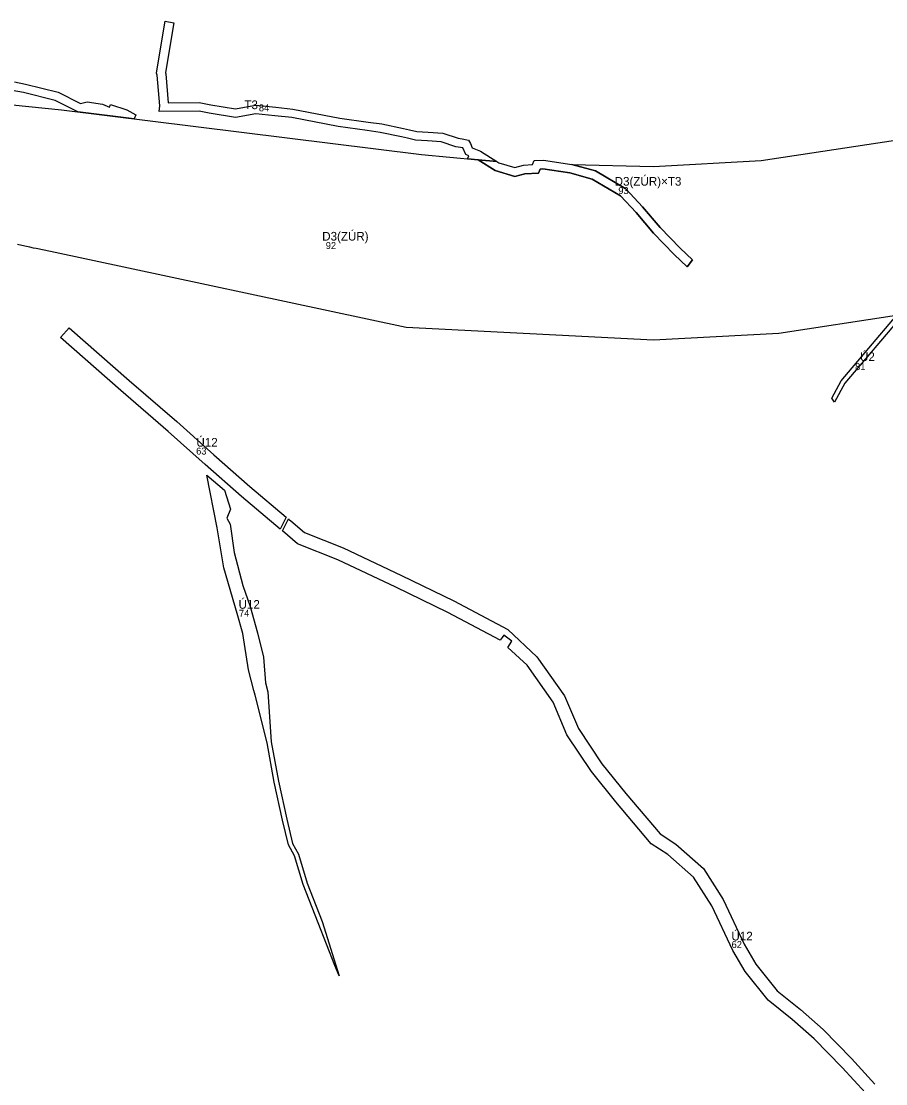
# Model space of a CAD drawing. Extents: x -521621 to -516857, y -1190025 to -1185894.
# Drawn here: x -519468 to -518471, y -1188636 to -1187411 of the extents above; entities that cross this region are included whole.
import ezdxf

# ---------------------------------------------------------------- set-up
doc = ezdxf.new("R2010")
doc.units = 0
for name, color, linetype in [('VPO_id', 7, 'Continuous'), ('VPO_n', 7, 'Continuous'), ('VPS_id', 7, 'Continuous'), ('VPS_n', 7, 'Continuous')]:
    doc.layers.add(name, color=color, linetype=linetype)

msp = doc.modelspace()

# ---------------------------------------------------------------- linework, layer by layer
at = {"layer": 'VPO_n'}
for points in [[(-518451.1, -1187749.3), (-518518.3, -1187828.7), (-518530, -1187850.3), (-518533.4, -1187846), (-518522.5, -1187825.9), (-518458.6, -1187750.5)], [(-519422.5, -1187776), (-519415.6, -1187768.2), (-519412.6, -1187764.7), (-519343.3, -1187825.6), (-519288.3, -1187872.8), (-519249.5, -1187907.6), (-519245.6, -1187911), (-519204.1, -1187947.8), (-519162.2, -1187983), (-519169.2, -1187996.7), (-519213.9, -1187959.1), (-519255.6, -1187922.2), (-519298.2, -1187884.1), (-519353.1, -1187836.9)], [(-519253.8, -1187934.5), (-519233.6, -1187951.8), (-519226.6, -1187973.9), (-519230.7, -1187984), (-519226.7, -1187990.9), (-519222.4, -1188023.6), (-519212.2, -1188061.6), (-519204, -1188086.1), (-519195.2, -1188116.4), (-519188.6, -1188144.5), (-519186.1, -1188173.9), (-519183.4, -1188184.3), (-519179.6, -1188242), (-519171.1, -1188287.2), (-519161.6, -1188331.1), (-519155.1, -1188358.9), (-519148.3, -1188371.3), (-519138.1, -1188404.6), (-519120.9, -1188448.8), (-519101.2, -1188511.7), (-519106.4, -1188499.6), (-519125.6, -1188450.6), (-519142.9, -1188406.3), (-519152.9, -1188373.2), (-519159.8, -1188360.8), (-519166.5, -1188332.2), (-519176, -1188288.2), (-519184.4, -1188243.1), (-519198.2, -1188188.1), (-519199.6, -1188182.6), (-519205.9, -1188159.1), (-519212.1, -1188117.2), (-519218.9, -1188094), (-519234, -1188041.5), (-519242, -1187995.2)]]:
    msp.add_lwpolyline(points, close=True, dxfattribs=at)
msp.add_lwpolyline([(-518494.6, -1188646.3), (-518521.3, -1188617.2), (-518553.6, -1188584.3), (-518578.9, -1188561.9), (-518606.8, -1188539.5), (-518633, -1188506.5), (-518647.5, -1188482.3), (-518671.6, -1188430.9), (-518692.6, -1188397.9), (-518722.2, -1188371.9), (-518741.4, -1188359.3), (-518782.4, -1188311.1), (-518810.5, -1188276.1), (-518838.6, -1188233.7), (-518854.5, -1188196.2), (-518884.6, -1188153.7), (-518906.7, -1188133.1), (-518902, -1188126), (-518906.7, -1188122.4), (-518911.4, -1188118.8), (-518913.4, -1188121.8), (-518915.5, -1188124.9), (-518975.8, -1188092.8), (-519035.8, -1188063.6), (-519102.8, -1188032), (-519149.1, -1188013.6), (-519166.7, -1187998.8), (-519159.8, -1187985), (-519159.6, -1187985.2), (-519157, -1187987.3), (-519141.3, -1188000.6), (-519096.8, -1188018.2), (-519029.3, -1188050.1), (-518969, -1188079.4), (-518906.7, -1188112.5), (-518873.2, -1188143.8), (-518841.3, -1188188.8), (-518825.3, -1188226.5), (-518798.4, -1188267.3), (-518770.9, -1188301.6), (-518731.3, -1188347.9), (-518713.1, -1188360), (-518681.1, -1188388), (-518658.4, -1188423.7), (-518634.3, -1188475.2), (-518620.7, -1188498), (-518596.1, -1188528.9), (-518569.2, -1188550.4), (-518543.2, -1188573.4), (-518510.4, -1188606.8), (-518483.5, -1188636.3)], dxfattribs=at)
at = {"layer": 'VPS_n'}
for points in [[(-519306.3, -1187438.7), (-519301.7, -1187411.4), (-519291.8, -1187413.4), (-519296.5, -1187440.4), (-519301.5, -1187470.9), (-519301.2, -1187472.1), (-519298.2, -1187505.3), (-519262.5, -1187504.9), (-519249.3, -1187507.6), (-519220.9, -1187512.2), (-519197.7, -1187508), (-519174.4, -1187510.5), (-519154.5, -1187512.6), (-519100.6, -1187523), (-519067.6, -1187527.6), (-519052.2, -1187529.7), (-519027.2, -1187534.9), (-519020.2, -1187536.4), (-519011.6, -1187538.6), (-518998.6, -1187539.3), (-518981.7, -1187540.5), (-518964.2, -1187546.2), (-518959.5, -1187546.9), (-518952.3, -1187548.3), (-518950, -1187552.2), (-518947.7, -1187557.3), (-518938.1, -1187561), (-518919.5, -1187573), (-518941, -1187571), (-518953.1, -1187569.9), (-518951.6, -1187566.5), (-518955.2, -1187565.1), (-518958.7, -1187557.3), (-518961.2, -1187556.8), (-518966.6, -1187556), (-518983.6, -1187550.4), (-518999.2, -1187549.3), (-519013.1, -1187548.5), (-519022.5, -1187546.1), (-519029.3, -1187544.6), (-519053.8, -1187539.6), (-519069, -1187537.5), (-519102.2, -1187532.8), (-519155.9, -1187522.5), (-519175.4, -1187520.4), (-519197.3, -1187518.1), (-519220.8, -1187522.3), (-519251.1, -1187517.4), (-519262.7, -1187515.1), (-519308.7, -1187515.4), (-519307.9, -1187508.8), (-519311.1, -1187473.6), (-519311.7, -1187471.1)], [(-518941, -1187571), (-518919.5, -1187573), (-518917.3, -1187574.4), (-518898.7, -1187580.1), (-518888.6, -1187577.2), (-518878.4, -1187576.7), (-518876.6, -1187571.9), (-518865.7, -1187571.6), (-518833.1, -1187576.5), (-518805.7, -1187584), (-518770.6, -1187604.7), (-518751.6, -1187625.3), (-518731.3, -1187649), (-518708, -1187673), (-518693.8, -1187686.5), (-518700.2, -1187694.3), (-518715.1, -1187680.2), (-518738.7, -1187655.7), (-518759, -1187631.9), (-518777, -1187612.5), (-518809.6, -1187593.3), (-518835.2, -1187586.3), (-518866.3, -1187581.6), (-518869.6, -1187581.7), (-518871.3, -1187586.4), (-518887, -1187587.1), (-518898.8, -1187590.5), (-518921.5, -1187583.6)]]:
    msp.add_lwpolyline(points, close=True, dxfattribs=at)
for points in [[(-519790.9, -1187475.7), (-519421.5, -1187513.5), (-519006.3, -1187565.1), (-518941, -1187571), (-518921.5, -1187583.6), (-518898.8, -1187590.5), (-518887, -1187587.1), (-518871.3, -1187586.4), (-518869.6, -1187581.7), (-518866.3, -1187581.6), (-518835.2, -1187586.3), (-518809.6, -1187593.3), (-518777, -1187612.5), (-518759, -1187631.9), (-518738.7, -1187655.7), (-518715.1, -1187680.2), (-518700.2, -1187694.3), (-518693.8, -1187686.5), (-518708, -1187673), (-518731.3, -1187649), (-518751.6, -1187625.3), (-518770.6, -1187604.7), (-518805.7, -1187584), (-518833.1, -1187576.5), (-518739, -1187578.8), (-518614.8, -1187572), (-518434.3, -1187544.5)], [(-519475.7, -1187481.4), (-519462.8, -1187483.9), (-519425.3, -1187493.2), (-519399.3, -1187506.3), (-519391.7, -1187504.3), (-519374.1, -1187506.8), (-519366.1, -1187510.6), (-519364.7, -1187507.5), (-519346.2, -1187513.6), (-519335.5, -1187519.3), (-519337.5, -1187523.9), (-519402.5, -1187515.9), (-519428.8, -1187502.6), (-519465, -1187493.7), (-519478.4, -1187491.1)], [(-518458.6, -1187750.5), (-518594.2, -1187771.1), (-518738.7, -1187779), (-519023.8, -1187764.4), (-519433.9, -1187676.7), (-519450.5, -1187673.5), (-519453.5, -1187672.8), (-519458, -1187671.8), (-519461.7, -1187670.9), (-519467.2, -1187669.7), (-519472.1, -1187668.6)]]:
    msp.add_lwpolyline(points, dxfattribs=at)

# ---------------------------------------------------------------- texts
at = {"layer": 'VPO_id'}
for s, p in [('81', (-518506.4, -1187813.5)), ('63', (-519266.1, -1187910.8)), ('74', (-519216.7, -1188097.7)), ('62', (-518648.8, -1188479.5))]:
    msp.add_text(s, height=8, dxfattribs=at).set_placement(p)
at = {"layer": 'VPO_n'}
for s, p in [('Ú2', (-518500.7, -1187803.1)), ('Ú12', (-519265.8, -1187901.7)), ('Ú12', (-519217.2, -1188088.5)), ('Ú12', (-518649, -1188470.8))]:
    msp.add_text(s, height=10, dxfattribs=at).set_placement(p)
at = {"layer": 'VPS_id'}
for s, p in [('84', (-519193.8, -1187515.2)), ('93', (-518779.4, -1187610.6)), ('92', (-519116.7, -1187673.9))]:
    msp.add_text(s, height=8, dxfattribs=at).set_placement(p)
at = {"layer": 'VPS_n'}
for s, p in [('T3', (-519210.5, -1187512.7)), ('D3(ZÚR)×T3', (-518783.6, -1187600.9)), ('D3(ZÚR)', (-519120.8, -1187664.2))]:
    msp.add_text(s, height=10, dxfattribs=at).set_placement(p)

doc.saveas('drawing.dxf')
